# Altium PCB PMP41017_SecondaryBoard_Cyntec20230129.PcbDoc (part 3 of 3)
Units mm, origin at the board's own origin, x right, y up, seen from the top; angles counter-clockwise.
Board outline 56.93 x 50 mm, 6 copper layers (Top Layer, Layer 1, Layer 3, Layer 4, Layer 2, Bottom Layer), stack 1.219 mm thick; 147 components, 63 nets, 876 pads, 1174 vias.
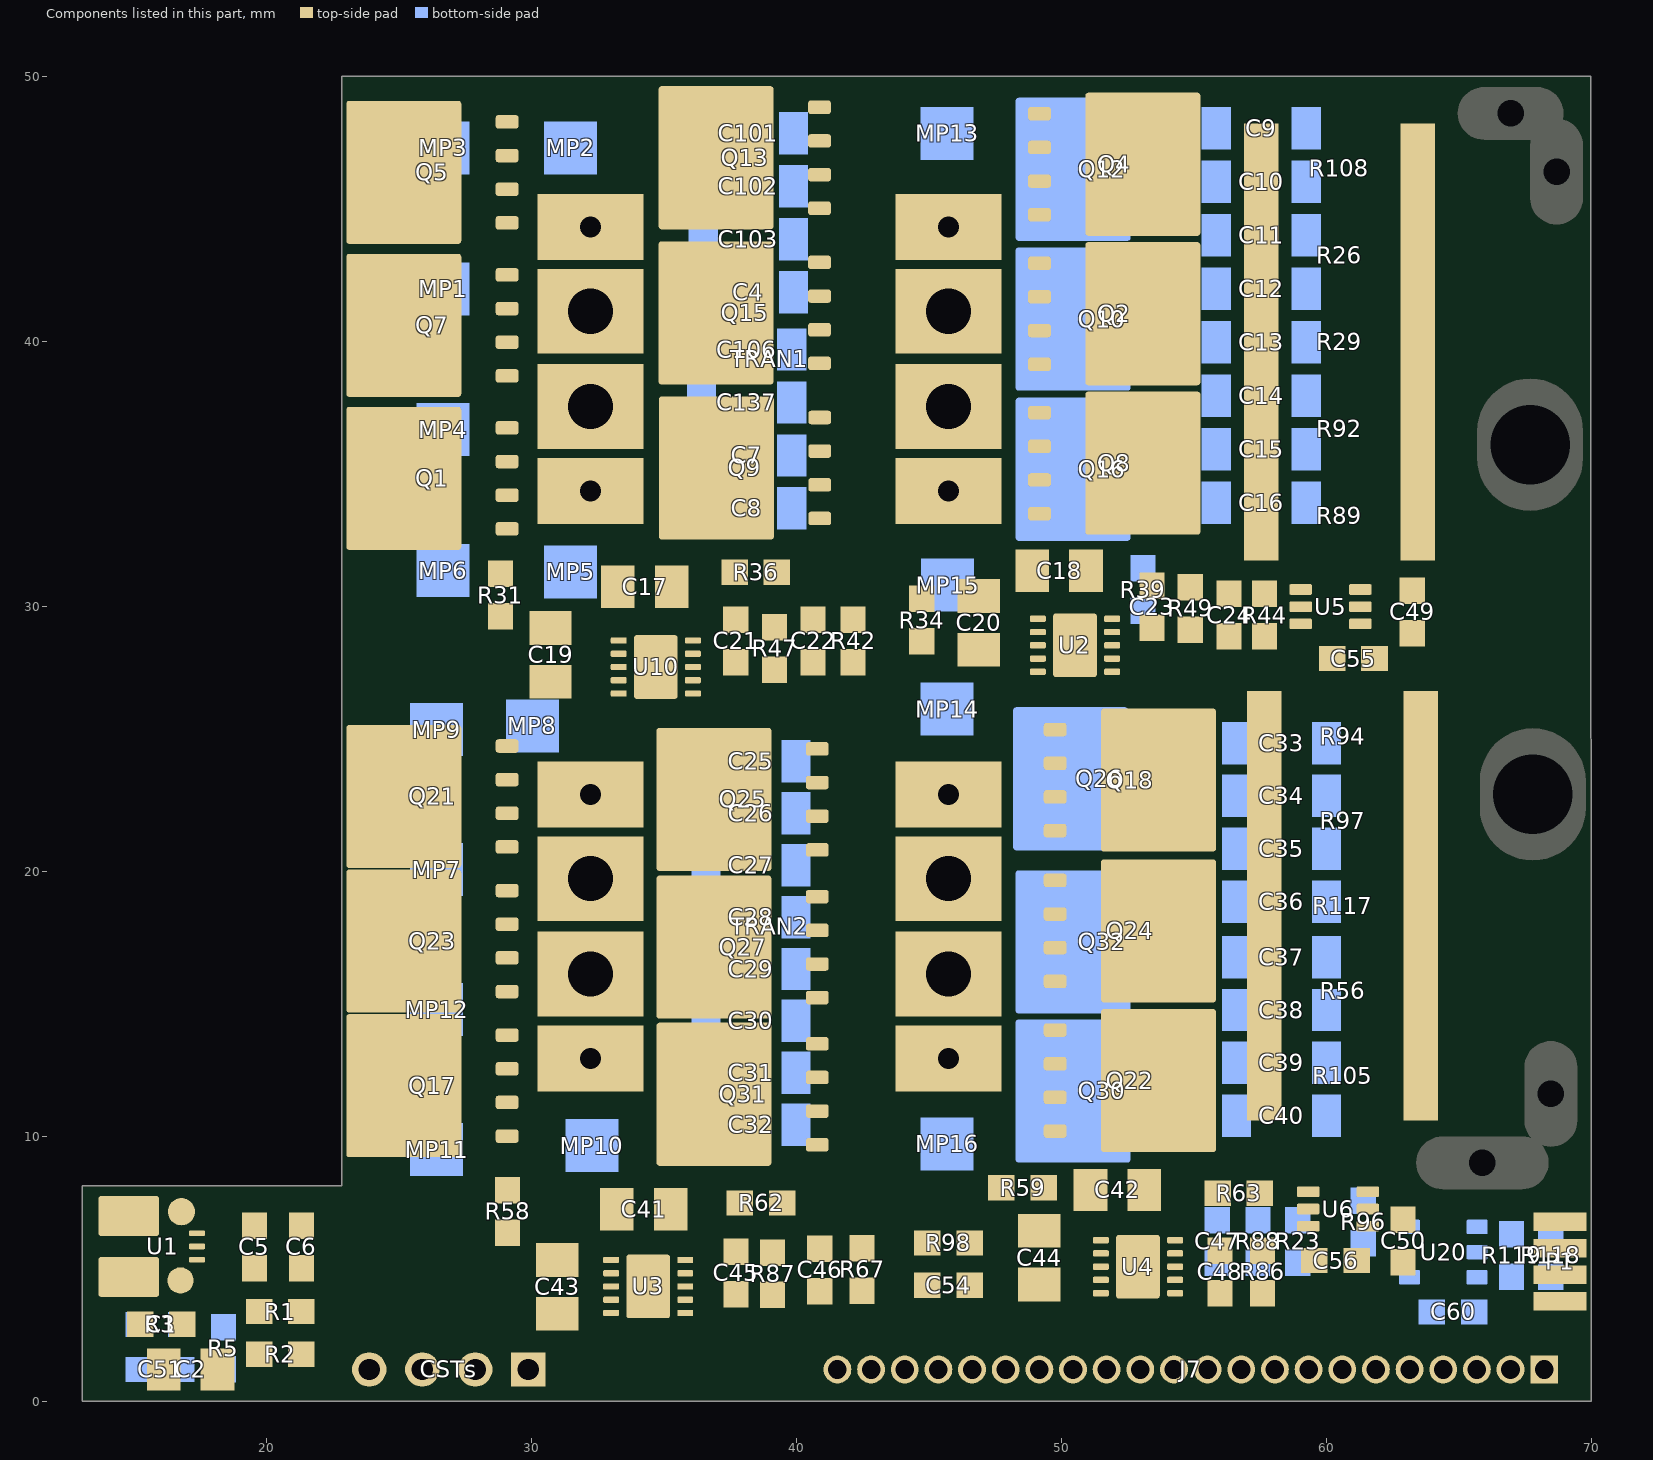
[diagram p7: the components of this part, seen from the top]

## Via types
v1: diameter 0.508, hole 0.254, Top Layer to Bottom Layer, tented both sides, 996 vias
v2: diameter 0.508, hole 0.254, Layer 2 to Bottom Layer, tented both sides, 151 vias
v3: diameter 0.508, hole 0.254, Top Layer to Bottom Layer, 14 vias
v4: diameter 0.5, hole 0.2, Top Layer to Bottom Layer, 12 vias
v5: diameter 0.762, hole 0.356, Top Layer to Bottom Layer, tented both sides, 1 vias

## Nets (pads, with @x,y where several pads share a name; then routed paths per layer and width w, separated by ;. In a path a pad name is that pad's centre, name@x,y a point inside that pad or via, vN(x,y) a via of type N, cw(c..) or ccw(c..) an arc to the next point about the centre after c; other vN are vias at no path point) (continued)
pads on no net: Q1.9@24.511,33.496 Q1.9@24.511,34.826 Q1.9@24.511,36.156 Q1.9@25.526,34.826 Q1.9@25.661,33.496 Q1.9@25.661,34.826 Q1.9@25.661,36.156 Q1.9@26.811,33.496 Q1.9@26.811,34.826 Q1.9@26.811,36.156 Q1.9@27.106,32.454 Q1.9@27.106,37.199 Q2.9@51.176,38.668 Q2.9@51.176,43.413 Q2.9@51.471,39.71 Q2.9@51.471,41.04 Q2.9@51.471,42.37 Q2.9@52.621,39.71 Q2.9@52.621,41.04 Q2.9@52.621,42.37 Q2.9@52.756,41.04 Q2.9@53.771,39.71 Q2.9@53.771,41.04 Q2.9@53.771,42.37 Q4.9@51.176,44.308 Q4.9@51.176,49.053 Q4.9@51.471,45.35 Q4.9@51.471,46.68 Q4.9@51.471,48.01 Q4.9@52.621,45.35 Q4.9@52.621,46.68 Q4.9@52.621,48.01 Q4.9@52.756,46.68 Q4.9@53.771,45.35 Q4.9@53.771,46.68 Q4.9@53.771,48.01 Q5.9@24.511,45.043 Q5.9@24.511,46.373 Q5.9@24.511,47.703 Q5.9@25.526,46.373 Q5.9@25.661,45.043 Q5.9@25.661,46.373 Q5.9@25.661,47.703 Q5.9@26.811,45.043 Q5.9@26.811,46.373 Q5.9@26.811,47.703 Q5.9@27.106,44.001 Q5.9@27.106,48.746 Q7.9@24.511,39.27 Q7.9@24.511,40.6 Q7.9@24.511,41.93 Q7.9@25.526,40.6 Q7.9@25.661,39.27 Q7.9@25.661,40.6 Q7.9@25.661,41.93 Q7.9@26.811,39.27 Q7.9@26.811,40.6 Q7.9@26.811,41.93 Q7.9@27.106,38.227 Q7.9@27.106,42.972 Q8.9@51.176,33.028 Q8.9@51.176,37.773 Q8.9@51.471,34.071 Q8.9@51.471,35.401 Q8.9@51.471,36.731 Q8.9@52.621,34.071 Q8.9@52.621,35.401 Q8.9@52.621,36.731 Q8.9@52.756,35.401 Q8.9@53.771,34.071 Q8.9@53.771,35.401 Q8.9@53.771,36.731 Q9.9@36.308,33.889 Q9.9@36.308,35.219 Q9.9@36.308,36.549 Q9.9@37.323,35.219 Q9.9@37.458,33.889 Q9.9@37.458,35.219 Q9.9@37.458,36.549 Q9.9@38.608,33.889 Q9.9@38.608,35.219 Q9.9@38.608,36.549 Q9.9@38.903,32.846 Q9.9@38.903,37.591 Q10.9@49.77,39.504 Q10.9@49.77,40.834 Q10.9@49.77,42.164 Q10.9@50.92,39.504 Q10.9@50.92,40.834 Q10.9@50.92,42.164 Q10.9@50.785,40.834 Q10.9@52.07,39.504 Q10.9@52.07,40.834 Q10.9@52.07,42.164 Q10.9@52.365,38.462 Q10.9@52.365,43.206 Q12.9@49.771,45.16 Q12.9@49.771,46.49 Q12.9@49.771,47.82 Q12.9@50.786,46.49 Q12.9@50.921,45.16 Q12.9@50.921,46.49 Q12.9@50.921,47.82 Q12.9@52.071,45.16 Q12.9@52.071,46.49 Q12.9@52.071,47.82 Q12.9@52.366,44.117 Q12.9@52.366,48.862 Q13.9@36.298,45.595 Q13.9@36.298,46.925 Q13.9@36.298,48.255 Q13.9@37.313,46.925 Q13.9@37.448,45.595 Q13.9@37.448,46.925 Q13.9@37.448,48.255 Q13.9@38.598,45.595 Q13.9@38.598,46.925 Q13.9@38.598,48.255 Q13.9@38.893,44.552 Q13.9@38.893,49.297 Q15.9@36.298,39.742 Q15.9@36.298,41.072 Q15.9@36.298,42.402 Q15.9@37.313,41.072 Q15.9@37.448,39.742 Q15.9@37.448,41.072 Q15.9@37.448,42.402 Q15.9@38.598,39.742 Q15.9@38.598,41.072 Q15.9@38.598,42.402 Q15.9@38.893,38.699 Q15.9@38.893,43.444 Q16.9@49.77,33.841 Q16.9@49.77,35.171 Q16.9@49.77,36.501 Q16.9@50.92,33.841 Q16.9@50.92,35.171 Q16.9@50.92,36.501 Q16.9@50.785,35.171 Q16.9@52.07,33.841 Q16.9@52.07,35.171 Q16.9@52.07,36.501 Q16.9@52.365,32.799 Q16.9@52.365,37.544 Q17.9@24.511,10.581 Q17.9@24.511,11.911 Q17.9@24.511,13.241 Q17.9@25.526,11.911 Q17.9@25.661,10.581 Q17.9@25.661,11.911 Q17.9@25.661,13.241 Q17.9@26.811,10.581 Q17.9@26.811,11.911 Q17.9@26.811,13.241 Q17.9@27.106,9.539 Q17.9@27.106,14.284 Q18.9@51.766,21.069 Q18.9@51.766,25.814 Q18.9@52.061,22.112 Q18.9@52.061,23.442 Q18.9@52.061,24.772 Q18.9@53.211,22.112 Q18.9@53.211,23.442 Q18.9@53.211,24.772 Q18.9@53.346,23.442 Q18.9@54.361,22.112 Q18.9@54.361,23.442 Q18.9@54.361,24.772 Q21.9@24.511,21.493 Q21.9@24.511,22.823 Q21.9@24.511,24.153 Q21.9@25.526,22.823 Q21.9@25.661,21.493 Q21.9@25.661,22.823 Q21.9@25.661,24.153 Q21.9@26.811,21.493 Q21.9@26.811,22.823 Q21.9@26.811,24.153 Q21.9@27.106,20.45 Q21.9@27.106,25.195 Q22.9@51.766,9.73 Q22.9@51.766,14.474 Q22.9@52.061,10.772 Q22.9@52.061,12.102 Q22.9@52.061,13.432 Q22.9@53.211,10.772 Q22.9@53.211,12.102 Q22.9@53.211,13.432 Q22.9@53.346,12.102 Q22.9@54.361,10.772 Q22.9@54.361,12.102 Q22.9@54.361,13.432 Q23.9@24.511,16.037 Q23.9@24.511,17.367 Q23.9@24.511,18.697 Q23.9@25.526,17.367 Q23.9@25.661,16.037 Q23.9@25.661,17.367 Q23.9@25.661,18.697 Q23.9@26.811,16.037 Q23.9@26.811,17.367 Q23.9@26.811,18.697 Q23.9@27.106,14.995 Q23.9@27.106,19.74 Q24.9@51.766,15.38 Q24.9@51.766,20.125 Q24.9@52.061,16.422 Q24.9@52.061,17.752 Q24.9@52.061,19.082 Q24.9@53.211,16.422 Q24.9@53.211,17.752 Q24.9@53.211,19.082 Q24.9@53.346,17.752 Q24.9@54.361,16.422 Q24.9@54.361,17.752 Q24.9@54.361,19.082 Q25.9@36.216,21.382 Q25.9@36.216,22.712 Q25.9@36.216,24.042 Q25.9@37.231,22.712 Q25.9@37.366,21.382 Q25.9@37.366,22.712 Q25.9@37.366,24.042 Q25.9@38.516,21.382 Q25.9@38.516,22.712 Q25.9@38.516,24.042 Q25.9@38.811,20.34 Q25.9@38.811,25.085 Q26.9@49.675,22.161 Q26.9@49.675,23.491 Q26.9@49.675,24.821 Q26.9@50.69,23.491 Q26.9@50.825,22.161 Q26.9@50.825,23.491 Q26.9@50.825,24.821 Q26.9@51.975,22.161 Q26.9@51.975,23.491 Q26.9@51.975,24.821 Q26.9@52.27,21.118 Q26.9@52.27,25.863 Q27.9@36.216,15.806 Q27.9@36.216,17.136 Q27.9@36.216,18.466 Q27.9@37.231,17.136 Q27.9@37.366,15.806 Q27.9@37.366,17.136 Q27.9@37.366,18.466 Q27.9@38.516,15.806 Q27.9@38.516,17.136 Q27.9@38.516,18.466 Q27.9@38.811,14.764 Q27.9@38.811,19.509 Q30.9@49.77,10.382 Q30.9@49.77,11.712 Q30.9@49.77,13.042 Q30.9@50.92,10.382 Q30.9@50.92,11.712 Q30.9@50.92,13.042 Q30.9@50.785,11.712 Q30.9@52.07,10.382 Q30.9@52.07,11.712 Q30.9@52.07,13.042 Q30.9@52.365,9.34 Q30.9@52.365,14.085 Q31.9@36.216,10.256 Q31.9@36.216,11.586 Q31.9@36.216,12.916 Q31.9@37.231,11.586 Q31.9@37.366,10.256 Q31.9@37.366,11.586 Q31.9@37.366,12.916 Q31.9@38.516,10.256 Q31.9@38.516,11.586 Q31.9@38.516,12.916 Q31.9@38.811,9.213 Q31.9@38.811,13.958 Q32.9@49.77,16.005 Q32.9@49.77,17.335 Q32.9@49.77,18.665 Q32.9@50.92,16.005 Q32.9@50.92,17.335 Q32.9@50.92,18.665 Q32.9@50.785,17.335 Q32.9@52.07,16.005 Q32.9@52.07,17.335 Q32.9@52.07,18.665 Q32.9@52.365,14.963 Q32.9@52.365,19.708 U1.2 U1.5 U2.2 U3.2 U4.2 U10.2
copper on no net:
  other v4: 14.329,6.492 14.829,6.492 15.329,6.492 14.329,7.492 14.829,7.492 15.329,7.492

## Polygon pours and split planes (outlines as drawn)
V0-out on Top Layer "TOP_LAYER_V0-OUT_P112" (solid, remove dead copper, pour order 112): 33.947,7.905 36.482,7.905 38.683,5.704 38.683,0.762 32.163,0.762 32.163,6.121
V0-out on Top Layer "TOP_LAYER_V0-OUT_P092" (solid, remove dead copper, pour order 92): 39.951,26.492 42.957,26.492 42.957,6.856 40.091,6.856
VDD on Top Layer "TOP_LAYER_VDD_P104" (solid, remove dead copper, pour order 104): 13.208,5.984 15.858,5.984 15.858,2.906 ccw(c15.965,2.906) 15.89,2.831 17.064,1.656 17.064,0.254 13.462,0.254 13.208,0.508
V0-out on Top Layer "TOP_LAYER_V0-OUT_P091" (solid, remove dead copper, pour order 91): 39.92,50 42.926,50 42.926,31.494 40.052,31.494
LV_SW1A on Top Layer "TOP_LAYER_LV_SW1A_P086" (solid, remove dead copper, pour order 86): 28.114,50 39.283,50 39.283,28.702 28.114,28.702
LV_SW2B on Top Layer "TOP_LAYER_LV_SW2B_P087" (solid, remove dead copper, pour order 87): 50.352,28.41 43.434,28.41 43.434,6.907 50.352,6.907
12Vo_B on Top Layer "TOP_LAYER_12VO_B_P085" (solid, remove dead copper, pour order 85): 22.924,28.094 29.864,28.094 29.864,2.634 22.943,2.634
LV_SW2A on Top Layer "TOP_LAYER_LV_SW2A_P082" (solid, remove dead copper, pour order 82): 28.193,27.906 39.624,27.906 39.624,5.749 28.352,5.749
12Vo_B on Top Layer "TOP_LAYER_12VO_B_P065" (solid, remove dead copper, pour order 65): 59.359,27.38 51.135,27.38 51.135,8.895 59.553,8.895 59.837,9.178 59.837,26.903
12Vout on Top Layer "TOP_LAYER_12VOUT_P055" (solid, remove dead copper, pour order 55): 60.627,10.479 64.206,10.479 67.814,14.087 69.74,14.087 69.74,16.013 69.74,43.568 67.814,43.568 64.32,47.062 64.32,50 60.627,50
LV_SW1B on Top Layer "TOP_LAYER_LV_SW1B_P049" (solid, remove dead copper, pour order 49): 49.897,49.823 43.18,49.823 43.18,31.494 49.897,31.494
V0-out on Top Layer "TOP_LAYER_V0-OUT_P070" (solid, remove dead copper, pour order 70): 62.758,7.786 62.758,9.955 66.655,13.851 69.74,13.851 69.74,8.78 68.746,7.786
V0-out on Top Layer "TOP_LAYER_V0-OUT_P052" (solid, remove dead copper, pour order 52): 64.539,49.846 64.539,47.171 67.927,43.782 69.85,43.782 69.85,49.338 69.342,49.846
12Vo_A on Top Layer "TOP_LAYER_12VO_A_P051" (solid, remove dead copper, pour order 51): 50.546,50 60.1,50 60.1,31.037 50.546,31.037
12Vo_A on Top Layer "TOP_LAYER_12VO_A_P044" (solid, remove dead copper, pour order 44): 22.81,50 27.686,50 27.686,28.414 22.964,28.414
V0-out on Bottom Layer "BOTTOM_LAYER_V0-OUT_P115" (solid, remove dead copper, pour order 115): 51.25,6.341 51.25,4.789 53.061,2.979 55.922,2.979 55.922,7 55.674,7.248 52.158,7.248
V0-out on Bottom Layer "BOTTOM_LAYER_V0-OUT_P114" (solid, remove dead copper, pour order 114): 48.179,29.852 48.179,27.66 48.721,27.117 53.545,27.117 53.545,30.447 53.297,30.695 49.022,30.695
12Vo_B on Bottom Layer "BOTTOM_LAYER_12VO_B_P083" (solid, remove dead copper, pour order 83): 22.924,27.995 32.655,27.995 34.219,25.878 37.726,25.878 37.726,2.251 22.944,2.251
V0-out on Bottom Layer "BOTTOM_LAYER_V0-OUT_P113" (solid, remove dead copper, pour order 113): 32.51,29.036 32.51,28.855 33.533,29.877 33.366,29.877 33.342,29.867
V0-out on Bottom Layer "BOTTOM_LAYER_V0-OUT_P113" (solid, remove dead copper, pour order 113): 33.054,28.97 33.054,27.418 34.173,26.299 37.726,26.299 37.726,29.629 37.478,29.877 33.961,29.877
V0-out on Bottom Layer "BOTTOM_LAYER_V0-OUT_P106" (solid, remove dead copper, pour order 106): 22.352,0.508 22.352,7.238 21.716,7.874 17.526,7.874 17.526,0.508
VDD on Bottom Layer "BOTTOM_LAYER_VDD_P103" (solid, remove dead copper, pour order 103): 13.462,1.016 13.462,7.874 17.053,7.874 17.053,0.508 13.97,0.508
12Vo_A on Bottom Layer "BOTTOM_LAYER_12VO_A_P089" (solid, remove dead copper, pour order 89): 22.94,28.189 32.696,28.189 33.909,30.253 37.726,30.253 37.726,49.409 22.924,49.409
LV_SW2B on Bottom Layer "BOTTOM_LAYER_LV_SW2B_P088" (solid, remove dead copper, pour order 88): 53.086,7.086 53.086,27.571 43.272,27.571 43.272,7.086
V0-out on Bottom Layer "BOTTOM_LAYER_V0-OUT_P053" (solid, remove dead copper, pour order 53): 53.848,50 57.15,50 57.15,29.108 53.848,29.108
V0-out on Bottom Layer "BOTTOM_LAYER_V0-OUT_P084" (solid, remove dead copper, pour order 84): 38.554,27.618 43.235,27.618 43.235,7.099 38.569,7.099
LV_SW1B on Bottom Layer "BOTTOM_LAYER_LV_SW1B_P050" (solid, remove dead copper, pour order 50): 53.086,31.059 53.086,49.913 43.656,49.913 43.656,28.087 47.752,28.087 47.752,29.698 48.864,31.059
V0-out on Bottom Layer "BOTTOM_LAYER_V0-OUT_P069" (solid, remove dead copper, pour order 69): 63.796,7.124 69.74,7.124 69.74,14.246 62.954,14.246 62.719,14.011 62.719,8.2
12Vout on Bottom Layer "BOTTOM_LAYER_12VOUT_P057" (solid, remove dead copper, pour order 57): 62.436,40.671 69.394,40.671 69.74,40.324 69.74,15.278 62.436,15.278
12Vo_B on Bottom Layer "BOTTOM_LAYER_12VO_B_P068" (solid, remove dead copper, pour order 68): 60.434,8.07 61.275,8.911 61.275,28.802 57.897,28.802 57.897,8.07
V0-out on Bottom Layer "BOTTOM_LAYER_V0-OUT_P067" (solid, remove dead copper, pour order 67): 53.477,28.802 57.426,28.802 57.427,8.07 53.477,8.07
V0-out on Bottom Layer "BOTTOM_LAYER_V0-OUT_P054" (solid, remove dead copper, pour order 54): 69.342,40.965 62.067,40.965 62.067,49.846 69.342,49.846 69.85,49.338 69.85,41.473
V0-out on Bottom Layer "BOTTOM_LAYER_V0-OUT_P046" (solid, remove dead copper, pour order 46): 38.603,27.758 43.23,27.759 43.23,49.547 42.709,50.068 38.603,50.068
12Vo_A on Bottom Layer "BOTTOM_LAYER_12VO_A_P056" (solid, remove dead copper, pour order 56): 61.616,29.082 61.616,50 57.607,50 57.607,29.082
12Vo_A on Bottom Layer "BOTTOM_LAYER_12VO_A_P045" (solid, remove dead copper, pour order 45): 22.999,49.846 33.101,49.846 33.8,49.148 33.8,30.325 32.655,29.181 24.425,29.181 23.014,30.592
V0-out on Layer 1 "LAYER_1_V0-OUT_P102" (solid, remove dead copper, pour order 102): 13.462,1.016 13.462,7.366 13.97,7.874 21.97,7.874 22.352,7.492 22.352,0.762 22.098,0.508 13.97,0.508
12Vo_A on Layer 1 "Layer 1-12Vo_A" (solid, remove dead copper, pour order 90): 22.95,28.873 58.908,28.873 60.565,30.53 60.565,49.938 60.503,50 28.987,50 23.584,50 22.95,49.366
V0-out on Layer 1 "LAYER_1_V0-OUT_P076" (solid, remove dead copper, pour order 76): 62.719,2.467 69.74,2.467 69.74,14.246 62.954,14.246 62.719,14.011
12Vout on Layer 1 "LAYER_1_12VOUT_P075" (solid, remove dead copper, pour order 75): 60.972,40.671 69.394,40.671 69.74,40.324 69.74,15.278 60.972,15.278
V0-out on Layer 1 "LAYER_1_V0-OUT_P074" (solid, remove dead copper, pour order 74): 69.342,40.965 60.972,40.965 60.972,49.846 69.342,49.846 69.85,49.338 69.85,41.473
12Vo_B on Layer 1 "LAYER_1_12VO_B_P071" (solid, remove dead copper, pour order 71): 22.82,3.194 59.203,3.194 60.566,4.557 60.566,28.194 22.907,28.194
VDD on Layer 2 "LAYER_2_VDD_P108" (solid, remove dead copper, pour order 108): 13.208,0.762 13.208,7.366 13.716,7.874 21.97,7.874 22.352,7.492 22.352,0.762 21.844,0.254 13.716,0.254
V0-out on Layer 2 "Layer 2-V0-out" (solid, remove dead copper, pour order 72): 39.116,2.24 69.981,2.24 69.981,16.98 64.269,16.98 63.782,17.467 63.781,41.022 69.98,41.022 69.98,50 39.116,50
12Vo_B on Layer 2 "LAYER_2_12VO_B_P080" (solid, remove dead copper, pour order 80): 38.354,2.29 38.354,29.122 23.373,29.122 22.952,28.7 22.952,2.333
12Vo_A on Layer 2 "LAYER_2_12VO_A_P079" (solid, remove dead copper, pour order 79): 39.116,29.375 39.116,49.746 38.862,50 23.584,50 22.95,49.366 22.95,29.421
12Vout on Layer 2 "LAYER_2_12VOUT_P073" (solid, remove dead copper, pour order 73): 69.996,17.267 64.401,17.267 63.885,17.783 63.885,40.771 69.791,40.771 69.981,40.581
LV_SW2A on Layer 4 "LAYER_4_LV_SW2A_P111" (solid, remove dead copper, pour order 111): 37.084,2.535 37.084,25.343 29.903,25.343 29.903,2.556
LV_SW1A on Layer 4 "LAYER_4_LV_SW1A_P110" (solid, remove dead copper, pour order 110): 37.084,25.837 37.084,50 29.972,50 29.903,49.931 29.903,25.857
VDD on Layer 4 "LAYER_4_VDD_P107" (solid, remove dead copper, pour order 107): 13.208,0.762 13.208,7.366 13.716,7.874 21.97,7.874 22.352,7.492 22.352,0.762 21.844,0.254 13.716,0.254
12Vout on Layer 4 "LAYER_4_12VOUT_P098" (solid, remove dead copper, pour order 98): 69.996,17.267 64.401,17.267 62.738,18.93 62.738,39.624 63.885,40.771 69.791,40.771 69.981,40.581
12Vo_B on Layer 4 "LAYER_4_12VO_B_P095" (solid, remove dead copper, pour order 95): 29.718,2.314 29.718,29.122 23.373,29.122 22.952,28.7 22.952,2.333
12Vo_A on Layer 4 "LAYER_4_12VO_A_P094" (solid, remove dead copper, pour order 94): 29.718,29.402 29.718,50 23.584,50 22.95,49.366 22.95,29.421
V0-out on Layer 4 "Layer 2-V0-out" (solid, remove dead copper, pour order 93): 37.338,2.24 69.981,2.24 69.981,16.98 64.269,16.98 62.423,18.826 62.422,39.662 63.781,41.022 69.98,41.022 69.98,50 37.338,50
VDD on Layer 3 "LAYER_3_VDD_P105" (solid, remove dead copper, pour order 105): 13.208,0.762 13.208,7.366 13.716,7.874 21.97,7.874 22.352,7.492 22.352,0.762 21.844,0.254 13.716,0.254
V0-out on Layer 3 "LAYER_3_V0-OUT_P101" (solid, remove dead copper, pour order 101): 61.144,2.994 69.74,2.994 69.74,14.246 61.084,14.246 61.084,3.053
12Vout on Layer 3 "LAYER_3_12VOUT_P100" (solid, remove dead copper, pour order 100): 60.972,40.671 69.394,40.671 69.74,40.324 69.74,15.278 60.972,15.278
V0-out on Layer 3 "LAYER_3_V0-OUT_P099" (solid, remove dead copper, pour order 99): 69.342,40.965 60.972,40.965 60.972,49.846 69.342,49.846 69.85,49.338 69.85,41.473
12Vo_A on Layer 3 "Layer 3-12Vo_A" (solid, remove dead copper, pour order 97): 22.95,28.873 58.908,28.873 60.565,30.53 60.565,49.938 60.503,50 28.987,50 23.584,50 22.95,49.366
12Vo_B on Layer 3 "LAYER_3_12VO_B_P096" (solid, remove dead copper, pour order 96): 22.817,2.286 60.174,2.286 60.566,2.678 60.566,28.194 22.907,28.194

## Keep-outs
Keep-Out Layer:
  text ".Layer_Name" at -20.343,-59.464 h1.52

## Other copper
Top Layer:
  text ".Layer_Name" at -20.343,-59.464 h1.52
Bottom Layer:
  text ".Layer_Name" at -20.343,-59.464 h1.52

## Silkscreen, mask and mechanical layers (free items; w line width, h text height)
Top Overlay:
  text "'.PRJ_Number'.PCB_Rev" at 116.739,-34.38 h2.75
  text ".Layer_Name" at -20.343,-59.464 h1.52
Bottom Overlay:
  text ".Layer_Name" at -20.343,-59.464 h1.52
Top Paste:
  text ".Layer_Name" at -20.343,-59.464 h1.52
Bottom Paste:
  text ".Layer_Name" at -20.343,-59.464 h1.52
Top Solder:
  text ".Layer_Name" at -20.343,-59.464 h1.52
  text ".Layer_Name" at -20.343,-59.464 h1.52
Bottom Solder:
  text ".Layer_Name" at -20.343,-59.464 h1.52
Drill Guide:
  text ".Layer_Name" at -20.343,-59.464 h1.52
M1 Board Outline:
  lines w0.1: 13.069,0 13.069,8.128 22.86,8.128 22.86,50 69.98,50 70,0 13.069,0 ; 69.98,0 69.98,0
  text ".Layer_Name" at -20.343,-59.464 h1.52
M2 Board Dimensions:
  rectangle: -34.999,-44.643 -31.824,-41.468
  rectangle: -31.824,-47.818 -22.299,-44.643
  lines w0.178: -34.999,-44.643 -9.599,-44.643 ; -31.824,-47.818 -31.824,-41.468 ; -28.649,-47.818 -28.649,-41.468 ; -22.299,-47.818 -22.299,-41.468 ; -15.949,-47.818 -15.949,-41.468 ; -34.999,-47.818 -9.599,-47.818 -9.599,-41.468 -34.999,-41.468 -34.999,-47.818
  text ".Layer_Name" at -20.343,-59.464 h1.52
M3 3D STEP Top:
  text ".Layer_Name" at -20.343,-59.464 h1.52
M4 3D STEP Bottom:
  text ".Layer_Name" at -20.343,-59.464 h1.52
M5 Assembly Top:
  lines w0.254: -42.416,-61.285 125.224,-61.285 ; -42.416,-56.12 125.275,-56.12 ; -42.416,-50.955 -42.416,-66.449 59.311,-66.449 125.275,-66.449 125.275,-50.955 -42.403,-50.955 -42.403,-66.449 -2.386,-66.449 ; 20.195,-66.449 20.195,-50.955 ; 52.377,-56.12 52.377,-50.955 ; 73.713,-56.12 73.713,-50.955 ; 89.512,-66.614 89.512,-61.463
  text "COMPONENTS MARKED 'DNP' SHOULD NOT BE POPULATED." at -5.7,-45.748 h1.52
  text "ASSEMBLY VARIANT:" at -5.713,-48.682 h1.52
  text ".VariantName" at 20.601,-48.682 h1.52
  text "PCB VIEWED FROM TOP SIDE" at -40.803,-54.312 h1.52
  text "BOARD #:" at 22.1,-54.312 h1.52
  text ".PRJ_Number" at 35.956,-54.312 h1.52
  text "REV:" at 57.406,-54.312 h1.52
  text ".PCB_Rev" at 64.81,-54.312 h1.52
  text "SVN REV:" at 78.691,-54.312 h1.52
  text ".VersionControl_RevNumber" at 91.544,-54.312 h1.52
  text "TID #:" at 22.1,-59.477 h1.52
  text ".TID" at 35.956,-59.477 h1.52
  text "PLOT NAME =" at -40.803,-64.693 h1.52
  text ".plot_File_Name" at -20.343,-64.693 h1.52
  text "GENERATED    :" at 22.151,-64.693 h1.52
  text ".Print_Date" at 44.236,-64.693 h1.52
  text ".Print_Time" at 62.753,-64.693 h1.52
  text "TEXAS INSTRUMENTS" at 94.871,-64.693 h1.52
M6 Assembly Bottom:
  lines w0.254: -42.429,-56.133 125.262,-56.133 ; -42.378,-61.297 125.262,-61.297 ; -6.665,-66.627 -6.665,-61.475 ; 9.133,-56.133 9.133,-50.968 ; 30.469,-56.133 30.469,-50.968 ; 62.651,-66.462 62.651,-50.968 ; 85.232,-66.462 125.249,-66.462 125.249,-50.968 -42.429,-50.968 -42.429,-66.462 23.535,-66.462 125.262,-66.462 125.262,-50.968
  text "COMPONENTS MARKED 'DNP' SHOULD NOT BE POPULATED." at 119.992,-45.736 h1.52
  text ".VariantName" at 93.474,-48.682 h1.52
  text "ASSEMBLY VARIANT:" at 119.865,-48.682 h1.52
  text ".VersionControl_RevNumber" at -8.697,-54.325 h1.52
  text "SVN REV:" at 4.155,-54.325 h1.52
  text ".PCB_Rev" at 18.036,-54.325 h1.52
  text "REV:" at 25.44,-54.325 h1.52
  text ".PRJ_Number" at 46.89,-54.325 h1.52
  text "BOARD #:" at 60.746,-54.325 h1.52
  text "PCB VIEWED FROM BOTTOM SIDE" at 123.649,-54.325 h1.52
  text ".TID" at 46.89,-59.49 h1.52
  text "TID #:" at 60.746,-59.49 h1.52
  text "TEXAS INSTRUMENTS" at -12.025,-64.705 h1.52
  text ".Print_Time" at 20.093,-64.705 h1.52
  text ".Print_Date" at 38.61,-64.705 h1.52
  text "GENERATED    :" at 60.695,-64.705 h1.52
  text ".plot_File_Name" at 103.19,-64.705 h1.52
  text "PLOT NAME =" at 123.649,-64.705 h1.52
M9 Title Sheet:
  drawing of 57 lines, arcs and shapes, not listed
  text "1" at -16.207,166.469 h1.78
  text "2" at 47.183,166.469 h1.78
  text "3" at 110.412,166.469 h1.78
  text "4" at 174.081,166.469 h1.78
  text "5" at 237.556,166.469 h1.78
  text "6" at 301.183,166.469 h1.78
  text "A" at -45.578,137.436 h1.78
  text "A" at 330.342,137.436 h1.78
  text "B" at -45.578,76.984 h1.78
  text "B" at 330.342,76.984 h1.78
  text "C" at -45.578,16.659 h1.78
  text "C" at 330.342,16.659 h1.78
  text "PROJECT TITLE:" at 253.126,-30.61 h1.14
  text ".PRJ_Title" at 254.396,-33.996 h1.78
  text "DESIGNED FOR:" at 253.126,-38.255 h1.14
  text ".PRJ_Customer" at 254.396,-41.811 h1.78
  text "D" at -45.578,-43.539 h1.78
  text "D" at 330.342,-43.539 h1.78
  text "FILE NAME:" at 253.126,-45.875 h1.14
  text ".PCB_File_Name_No_Path" at 254.396,-48.923 h1.78
  text "Texas Instruments (TI) and/or its licensors do not warrant the accuracy or completeness of this specification" at 126.9,-53.034 h1.14
  text "ENGINEER:" at 253.126,-53.241 h1.14
  text "LAYOUT BY:" at 291.353,-53.241 h1.14
  text "or any information contained therein. TI and/or its licensors do not warrant that this design will meet" at 125.758,-55.896 h1.14
  text ".PRJ_Engineer" at 254.396,-57.178 h1.78
  text ".PCB_Layout" at 292.635,-57.178 h1.78
  text "the specifications, will be suitable for your application or fit for any particular purpose, or will operate in" at 125.758,-58.757 h1.14
  text ".Layer_Name" at -20.343,-59.464 h1.52
  text "ALTIUM DESIGNER VERSION:" at 291.353,-61.115 h1.14
  text "an implementation. TI and/or its licensors do not warrant that the design is production worthy. You should" at 125.758,-61.619 h1.14
  text "completely validate and test your design implementation to confirm the system functionality for your application." at 126.9,-64.481 h1.14
  text ".print_Scale" at 254.396,-64.502 h1.78
  text ".Application_BuildNumber" at 292.635,-64.502 h1.78
  text "1" at -16.207,-69.751 h1.78
  text "2" at 47.183,-69.751 h1.78
  text "3" at 110.412,-69.751 h1.78
  text "4" at 174.081,-69.751 h1.78
  text "5" at 237.556,-69.751 h1.78
  text "6" at 301.183,-69.751 h1.78
M10 Fab Notes:
  drawing of 189 lines, arcs and shapes, not listed
  text "DESIGN INFORMATION" at 279.504,123.788 h1.52
  text "MIN. TRACK WIDTH:" at 263.132,120.432 h1.52
  text "8" at 290.977,120.432 h1.52
  text "MIL" at 294.908,120.432 h1.52
  text "7.874" at 286.751,117.342 h1.52
  text "MIN. CLEARANCE:" at 263.132,117.28 h1.52
  text "MIL" at 294.908,117.28 h1.52
  text "MIN. VIA PAD SIZE:" at 263.132,114.127 h1.52
  text "24" at 290.215,114.127 h1.52
  text "MIL" at 294.908,114.127 h1.52
  text "0.05mm (2MIL)" at 280.785,110.827 h1.52
  text "MINIMUM ANNULAR RING" at 254.77,110.618 h1.52
  text "EXTERNAL" at 298.769,110.618 h1.52
  text "PER" at 259.85,107.821 h1.52
  text "IPC-D-275 CLASS 2 LEVEL C" at 265.438,107.821 h1.52
  text "MIL, HOLES" at 303.239,105.269 h1.52
  text "+/-" at 293.27,105.051 h1.52
  text "+/-" at 314.962,105.051 h1.52
  text "REGISTRATION TOLERANCES:" at 254.77,105.024 h1.52
  text "METAL" at 285.244,105.024 h1.52
  text "5" at 299.88,105.024 h1.52
  text "3" at 321.038,105.024 h1.52
  text "MIL" at 323.991,105.024 h1.52
  text "HOLE SIZE TOLERANCE (UNLESS OTHERWISE SPECIFIED):" at 254.77,102.527 h1.52
  text "+/-" at 314.962,102.454 h1.52
  text "3" at 321.038,102.427 h1.52
  text "MIL" at 323.991,102.427 h1.52
  text "MATERIAL:" at 252.871,98.931 h1.52
  text "FR-4 High Tg" at 277.926,95.666 h1.52
  text "X" at 274.258,95.463 h1.52
  text "FR-408" at 263.564,95.348 h1.52
  text "OTHER" at 301.359,95.348 h1.52
  text "62 MIL (1.6mm) +/-10%" at 271.695,91.715 h1.52
  text "X" at 268.644,91.653 h1.52
  text "THICKNESS:" at 254.77,91.507 h1.52
  text "OTHER" at 304.331,91.507 h1.52
  text "TOLERANCE:" at 254.77,87.993 h1.52
  text "X" at 276.315,87.993 h1.52
  text "ANSI IPC-6012 TYPE 3 CLASS 2" at 280.837,87.993 h1.52
  text "OTHER +/-" at 280.836,84.331 h1.52
  text "BOW & TWIST:" at 254.77,80.643 h1.52
  text "X" at 276.315,80.643 h1.52
  text "ANSI IPC-6012 TYPE 3 CLASS 2" at 280.837,80.643 h1.52
  text "OTHER +/-" at 280.836,76.917 h1.52
  text "DRILLING:" at 252.871,73.599 h1.52
  text "NC_DRILL FILES" at 297.6,70.928 h1.52
  text "REFERENCE:" at 254.77,70.828 h1.52
  text "X" at 271.464,70.825 h1.52
  text "AS SHOWN" at 275.985,70.828 h1.52
  text "X" at 294.349,70.828 h1.52
  text "OTHER" at 305.169,67.214 h1.52
  text "PTH COPPER THICKNESS:" at 254.762,67.125 h1.52
  text "X" at 283.698,67.125 h1.52
  text "20-30 um" at 286.949,67.125 h1.52
  text "BOARD FINISH:" at 252.871,63.376 h1.52
  text "SILKSCREEN:" at 256.813,60.579 h1.52
  text "X" at 281.141,60.579 h1.52
  text "TOP" at 284.113,60.579 h1.52
  text "X" at 294.095,60.579 h1.52
  text "BOTTOM" at 297.092,60.579 h1.52
  text "SILKSCREEN COLOR:" at 256.813,56.637 h1.52
  text "X" at 281.116,56.637 h1.52
  text "WHITE" at 284.113,56.637 h1.52
  text "OTHER" at 297.092,56.637 h1.52
  text "X" at 284.443,52.993 h1.52
  text "GREEN" at 287.44,52.993 h1.52
  text "OTHER" at 303.137,52.993 h1.52
  text "SOLDER RESIST COLOR:" at 256.813,52.819 h1.52
  text "X" at 284.443,49.075 h1.52
  text "MATTE" at 287.44,49.075 h1.52
  text "SEMI-GLOSS" at 303.126,49.059 h1.52
  text "IMMERSION GOLD (ENIG)" at 279.82,44.687 h1.52
  text "ENEPIG" at 313.794,44.503 h1.52
  text "SURFACE FINISH:" at 252.871,44.478 h1.52
  text "X" at 275.299,44.478 h1.52
  text "IMM. TIN/SILVER OR EQUIV" at 261.241,40.99 h1.52
  text "OTHER" at 297.6,40.89 h1.52
  text "ARRAY/PANEL:" at 252.871,36.944 h1.52
  text "CUT AND TRIM PER M1 BOARD OUTLINE" at 279.82,36.735 h1.52
  text "N.C. ROUTE" at 279.82,33.281 h1.52
  text "X" at 297.295,33.281 h1.52
  text "V. SCORE" at 301.817,33.281 h1.52
  text "CERTIFICATION:" at 252.871,30.001 h1.52
  text "MATERIALS AND WORKMANSHIP FOR ALL PCBS" at 271.286,30.001 h1.52
  text "TO MEET OR EXCEED THE REQUIREMENTS OF:" at 271.286,27.612 h1.52
  text "X" at 262.078,24.345 h1.52
  text "ANSI IPC-A-600F CLASS ->" at 265.33,24.345 h1.52
  text "X" at 307.189,24.345 h1.52
  text "2" at 309.983,24.345 h1.52
  text "1" at 301.982,24.307 h1.52
  text "3" at 318.974,24.307 h1.52
  text "X" at 282.703,20.594 h1.52
  text "RoHS" at 285.954,20.594 h1.52
  text "OTHER" at 302.322,20.594 h1.52
  text "PER ORDER" at 312.407,20.594 h1.52
  text "ALL BOARDS MUST MEET OR EXCEED UL94-V0 REQUIREMENTS." at 253.57,16.687 h1.52
  text "PCB MUST BEAR THE UL94V-0 UL REGISTERED MATERIAL ID NUMBER" at 253.57,13.739 h1.52
  text "ADDITIONAL REQUIREMENTS:" at 252.871,9.435 h1.52
  text "MICROSECTION:" at 254.77,6.714 h1.52
  text "YES" at 277.776,6.714 h1.52
  text "REQUIRED" at 299.658,3.048 h1.52
  text "BARE BOARD ELEC. TEST:" at 254.77,2.976 h1.52
  text "NONE" at 287.936,2.976 h1.52
  text "X" at 296.66,2.976 h1.52
  text "PER ORDER" at 314.694,2.976 h1.52
  text "XX MIL VIAS REQUIRE NON-CONDUCTIVE FILL AND PLANARIZE" at 259.041,-2.23 h1.5
  text "XX MIL VIAS REQUIRE CONDUCTIVE FILL AND PLANARIZE" at 259.244,-4.871 h1.52
  text "OUTER XX MIL TRACES REQUIRE 50 OHM SINGLE-ENDED IMPEDANCE" at 259.219,-9.021 h1.47
  text "LAYER 2 & 3 (INNER LAYERS) XX MIL WIDE, XX MIL SPACE / TRACES REQUIRE 100 OHM DIFFERENTIAL IMPEDANCE" at 259.016,-15.008 h1.52
  text ".Layer_Name" at -20.343,-59.464 h1.52
M11 Gerber Information:
  lines w0.254: -42.416,-61.285 125.224,-61.285 ; -42.416,-56.12 125.275,-56.12 ; -42.416,-50.955 -42.416,-66.449 59.311,-66.449 125.275,-66.449 125.275,-50.955 -42.403,-50.955 -42.403,-66.449 -2.386,-66.449 ; 20.195,-66.449 20.195,-50.955 ; 52.377,-56.12 52.377,-50.955 ; 73.713,-56.12 73.713,-50.955 ; 89.512,-66.614 89.512,-61.463
  text "ALL ARTWORK VIEWED FROM TOP SIDE" at -40.803,-54.312 h1.52
  text "BOARD #:" at 22.1,-54.312 h1.52
  text ".PRJ_Number" at 35.956,-54.312 h1.52
  text "REV:" at 57.406,-54.312 h1.52
  text ".PCB_Rev" at 64.81,-54.312 h1.52
  text "SVN REV:" at 78.691,-54.312 h1.52
  text ".VersionControl_RevNumber" at 91.544,-54.312 h1.52
  text "LAYER NAME =" at -40.803,-59.464 h1.52
  text "TID #:" at 22.1,-59.477 h1.52
  text ".TID" at 35.956,-59.477 h1.52
  text "PLOT NAME =" at -40.803,-64.693 h1.52
  text ".plot_File_Name" at -20.343,-64.693 h1.52
  text "GENERATED    :" at 22.151,-64.693 h1.52
  text ".Print_Date" at 44.236,-64.693 h1.52
  text ".Print_Time" at 62.753,-64.693 h1.52
  text "TEXAS INSTRUMENTS" at 94.871,-64.693 h1.52
M12 Stackup:
  drawing of 441 lines, arcs and shapes, not listed
  text "Layer" at 214.469,162.365 h1.52
  text "Name" at 224.881,162.365 h1.52
  text "Material" at 248.497,162.365 h1.52
  text "Thickness" at 270.335,162.365 h1.52
  text "Constant" at 286.841,162.365 h1.52
  text "Board Layer Stack" at 301.315,162.365 h1.52
  text "Top Overlay" at 224.881,159.317 h1.52
  text "Top Solder" at 224.881,156.269 h1.52
  text "Solder Resist" at 248.497,156.269 h1.52
  text "0.40mil" at 270.335,156.269 h1.52
  text "3.5" at 286.841,156.269 h1.52
  text "1" at 214.469,153.221 h1.52
  text "Top Layer" at 224.881,153.221 h1.52
  text "CF-005" at 248.497,153.221 h1.52
  text "4.13mil" at 270.335,153.221 h1.52
  text "Dielectric 1" at 224.881,150.173 h1.52
  text "PP-006" at 248.497,150.173 h1.52
  text "2.80mil" at 270.335,150.173 h1.52
  text "4.1" at 286.841,150.173 h1.52
  text "2" at 214.469,147.125 h1.52
  text "Layer 1" at 224.881,147.125 h1.52
  text "CF-005" at 248.497,147.125 h1.52
  text "4.13mil" at 270.335,147.125 h1.52
  text "Dielectric 3" at 224.881,144.077 h1.52
  text "PP-006" at 248.497,144.077 h1.52
  text "2.80mil" at 270.335,144.077 h1.52
  text "4.1" at 286.841,144.077 h1.52
  text "3" at 214.469,141.029 h1.52
  text "Layer 3" at 224.881,141.029 h1.52
  text "CF-004" at 248.497,141.029 h1.52
  text "4.13mil" at 270.335,141.029 h1.52
  text "Dielectric1" at 224.881,137.981 h1.52
  text "Core-030" at 248.497,137.981 h1.52
  text "12.00mil" at 270.335,137.981 h1.52
  text "4.3" at 286.841,137.981 h1.52
  text "4" at 214.469,134.933 h1.52
  text "Layer 4" at 224.881,134.933 h1.52
  text "CF-004" at 248.497,134.933 h1.52
  text "4.13mil" at 270.335,134.933 h1.52
  text "Dielectric 4" at 224.881,131.885 h1.52
  text "PP-006" at 248.497,131.885 h1.52
  text "2.80mil" at 270.335,131.885 h1.52
  text "4.1" at 286.841,131.885 h1.52
  text "5" at 214.469,128.837 h1.52
  text "Layer 2" at 224.881,128.837 h1.52
  text "CF-005" at 248.497,128.837 h1.52
  text "4.13mil" at 270.335,128.837 h1.52
  text "Dielectric 2" at 224.881,125.789 h1.52
  text "PP-006" at 248.497,125.789 h1.52
  text "2.80mil" at 270.335,125.789 h1.52
  text "4.1" at 286.841,125.789 h1.52
  text "6" at 214.469,122.741 h1.52
  text "Bottom Layer" at 224.881,122.741 h1.52
  text "CF-005" at 248.497,122.741 h1.52
  text "4.13mil" at 270.335,122.741 h1.52
  text "Bottom Solder" at 224.881,119.693 h1.52
  text "Solder Resist" at 248.497,119.693 h1.52
  text "0.40mil" at 270.335,119.693 h1.52
  text "3.5" at 286.841,119.693 h1.52
  text "Bottom Overlay" at 224.881,116.645 h1.52
  text "GaN Board2" at 7.848,45.352 h0.89
  text "Transformer1" at 32.648,38.752 h0.89
  text "Resonant Choke 1&2" at 3.648,33.652 h0.89
  text "Board_CST" at 7.178,20.129 h0.89
  text "Transformer2" at 33.322,17.69 h0.89
  text "GaN Board1" at 6.448,12.152 h0.89
  text "Flyback" at 12.657,4.449 h0.89
  text "McU Board" at 49.457,2.352 h0.89
  text "Transformer2" at 38.928,-9.18 h0.89
  text ".Layer_Name" at -20.343,-59.464 h1.52
M13 Component Bodies Top:
  text ".Layer_Name" at -20.343,-59.464 h1.52
M14 Component Bodies Bottom:
  text ".Layer_Name" at -20.343,-59.464 h1.52
M15 Courtyards Top:
  text ".Layer_Name" at -20.343,-59.464 h1.52
M16 Courtyards Bottom:
  text ".Layer_Name" at -20.343,-59.464 h1.52
Drill Drawing:
  circle w0.254: c92.476,40.852 r0.702
  lines w0.254: 91.775,21.555 92.125,21.555 92.125,21.204 92.827,21.204 92.827,21.555 93.178,21.555 93.178,22.256 92.827,22.256 92.827,22.607 92.125,22.607 92.125,22.256 91.775,22.256 91.775,21.555 ; 91.775,24.362 91.775,24.712 92.125,25.063 91.775,25.414 91.775,25.765 92.125,25.765 92.476,25.414 92.827,25.765 93.178,25.765 93.178,25.414 92.827,25.063 93.178,24.712 93.178,24.362 92.827,24.362 92.476,24.712 92.125,24.362 91.775,24.362 ; 91.775,27.87 92.125,27.87 92.125,27.519 92.827,27.519 92.827,27.87 93.178,27.87 93.178,28.572 92.827,28.572 92.827,28.923 92.125,28.923 92.125,28.572 91.775,28.572 91.775,27.87 ; 91.775,33.835 91.775,34.186 92.125,34.537 91.775,34.887 91.775,35.238 92.125,35.238 92.476,34.887 92.827,35.238 93.178,35.238 93.178,34.887 92.827,34.537 93.178,34.186 93.178,33.835 92.827,33.835 92.476,34.186 92.125,33.835 91.775,33.835 ; 91.775,38.396 93.178,38.396 92.476,36.993 91.775,38.396 ; 91.775,43.308 93.178,43.308 93.178,44.711 91.775,44.711 91.775,43.308 ; 92.055,28.011 92.266,28.011 92.266,27.8 92.687,27.8 92.687,28.011 92.897,28.011 92.897,28.432 92.687,28.432 92.687,28.642 92.266,28.642 92.266,28.432 92.055,28.432 92.055,28.011 ; 92.055,34.115 92.055,34.326 92.266,34.537 92.055,34.747 92.055,34.958 92.266,34.958 92.476,34.747 92.687,34.958 92.897,34.958 92.897,34.747 92.687,34.537 92.897,34.326 92.897,34.115 92.687,34.115 92.476,34.326 92.266,34.115 92.055,34.115
  lines w0.305: 90.502,13.941 172.582,13.941 ; 90.502,45.518 172.582,45.518 ; 99.084,10.783 99.084,48.676 ; 107.517,10.783 107.517,48.676 ; 123.685,10.783 123.685,48.676 ; 130.268,10.783 130.268,48.676 ; 139.797,10.783 139.797,48.676 ; 158.195,10.783 158.195,48.676 ; 90.502,10.783 172.582,10.783 172.582,48.676 90.502,48.676 90.502,10.783
  text "Symbol" at 92.397,46.466 h1.83
  text "Quantity" at 100.031,46.466 h1.83
  text "Finished Hole Size" at 108.464,46.466 h1.83
  text "Plated" at 124.633,46.466 h1.83
  text "Hole Type" at 131.215,46.466 h1.83
  text "Drill Layer Pair" at 140.744,46.466 h1.83
  text "Hole Tolerance" at 159.142,46.466 h1.83
  text "12" at 100.031,43.308 h1.52
  text "7.87mil (0.200mm)" at 108.464,43.308 h1.52
  text "PTH" at 124.633,43.308 h1.52
  text "Round" at 131.215,43.308 h1.52
  text "Top Layer - Bottom Layer" at 140.744,43.308 h1.52
  text "1161" at 100.031,40.15 h1.52
  text "10.00mil (0.254mm)" at 108.464,40.15 h1.52
  text "PTH" at 124.633,40.15 h1.52
  text "Round" at 131.215,40.15 h1.52
  text "(Mixed)" at 140.744,40.15 h1.52
  text "1" at 100.031,36.993 h1.52
  text "14.00mil (0.356mm)" at 108.464,36.993 h1.52
  text "PTH" at 124.633,36.993 h1.52
  text "Round" at 131.215,36.993 h1.52
  text "Top Layer - Bottom Layer" at 140.744,36.993 h1.52
  text "22" at 100.031,33.835 h1.52
  text "27.56mil (0.700mm)" at 108.464,33.835 h1.52
  text "PTH" at 124.633,33.835 h1.52
  text "Round" at 131.215,33.835 h1.52
  text "Top Layer - Bottom Layer" at 140.744,33.835 h1.52
  text "4" at 100.031,30.677 h1.52
  text "31.89mil (0.810mm)" at 108.464,30.677 h1.52
  text "PTH" at 124.633,30.677 h1.52
  text "Round" at 131.215,30.677 h1.52
  text "Top Layer - Bottom Layer" at 140.744,30.677 h1.52
  text "+/-1.97mil" at 159.142,30.677 h1.52
  text "I" at 91.988,30.423 h1.4
  text "2" at 100.031,27.519 h1.52
  text "118.11mil (3.000mm)" at 108.464,27.519 h1.52
  text "PTH" at 124.633,27.519 h1.52
  text "Round" at 131.215,27.519 h1.52
  text "Top Layer - Bottom Layer" at 140.744,27.519 h1.52
  text "8" at 100.031,24.362 h1.52
  text "31.50mil (0.800mm)" at 108.464,24.362 h1.52
  text "PTH" at 124.633,24.362 h1.52
  text "Rectangle" at 131.215,24.362 h1.52
  text "Top Layer - Bottom Layer" at 140.744,24.362 h1.52
  text "8" at 100.031,21.204 h1.52
  text "66.93mil (1.700mm)" at 108.464,21.204 h1.52
  text "PTH" at 124.633,21.204 h1.52
  text "Rectangle" at 131.215,21.204 h1.52
  text "Top Layer - Bottom Layer" at 140.744,21.204 h1.52
  text "3" at 100.031,18.046 h1.52
  text "39.37mil (1.000mm)" at 108.464,18.046 h1.52
  text "PTH" at 124.633,18.046 h1.52
  text "Slot" at 131.215,18.046 h1.52
  text "Top Layer - Bottom Layer" at 140.744,18.046 h1.52
  text "A" at 91.755,17.792 h1.4
  text "1" at 100.031,14.888 h1.52
  text "39.37mil (1.000mm)" at 108.464,14.888 h1.52
  text "PTH" at 124.633,14.888 h1.52
  text "Slot" at 131.215,14.888 h1.52
  text "Top Layer - Bottom Layer" at 140.744,14.888 h1.52
  text "G" at 91.755,14.635 h1.4
  text "1222 Total" at 100.031,11.731 h1.52
  text "Slot definitions :" at 92.397,9.52 h1.52
  text "Routed Path Length" at 103.845,9.52 h1.52
  text "= Calculated from tool start centre position to tool end centre position." at 117.554,9.52 h1.52
  text "Hole Length" at 103.845,8.257 h1.52
  text "= Routed Path Length + Tool Size = Slot length as defined in the PCB layout" at 112.48,8.257 h1.52
  text ".Layer_Name" at -20.343,-59.464 h1.52
M17 Embedded Cavity:
  text ".Layer_Name" at -20.343,-59.464 h1.52
M18 Embedded Assembly:
  text ".Layer_Name" at -20.343,-59.464 h1.52
M19 Embedded Keepout:
  text ".Layer_Name" at -20.343,-59.464 h1.52

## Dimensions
0,0 to 22.86,50 on M2 Board Dimensions
-0.005,-0.017 to 70.005,0 on M2 Board Dimensions
-34.999,-47.818 to -9.599,-47.818 on M2 Board Dimensions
